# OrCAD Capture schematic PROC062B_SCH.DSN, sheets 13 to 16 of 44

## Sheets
13 12. SoC POWER2: size C; title: SoC POWER2
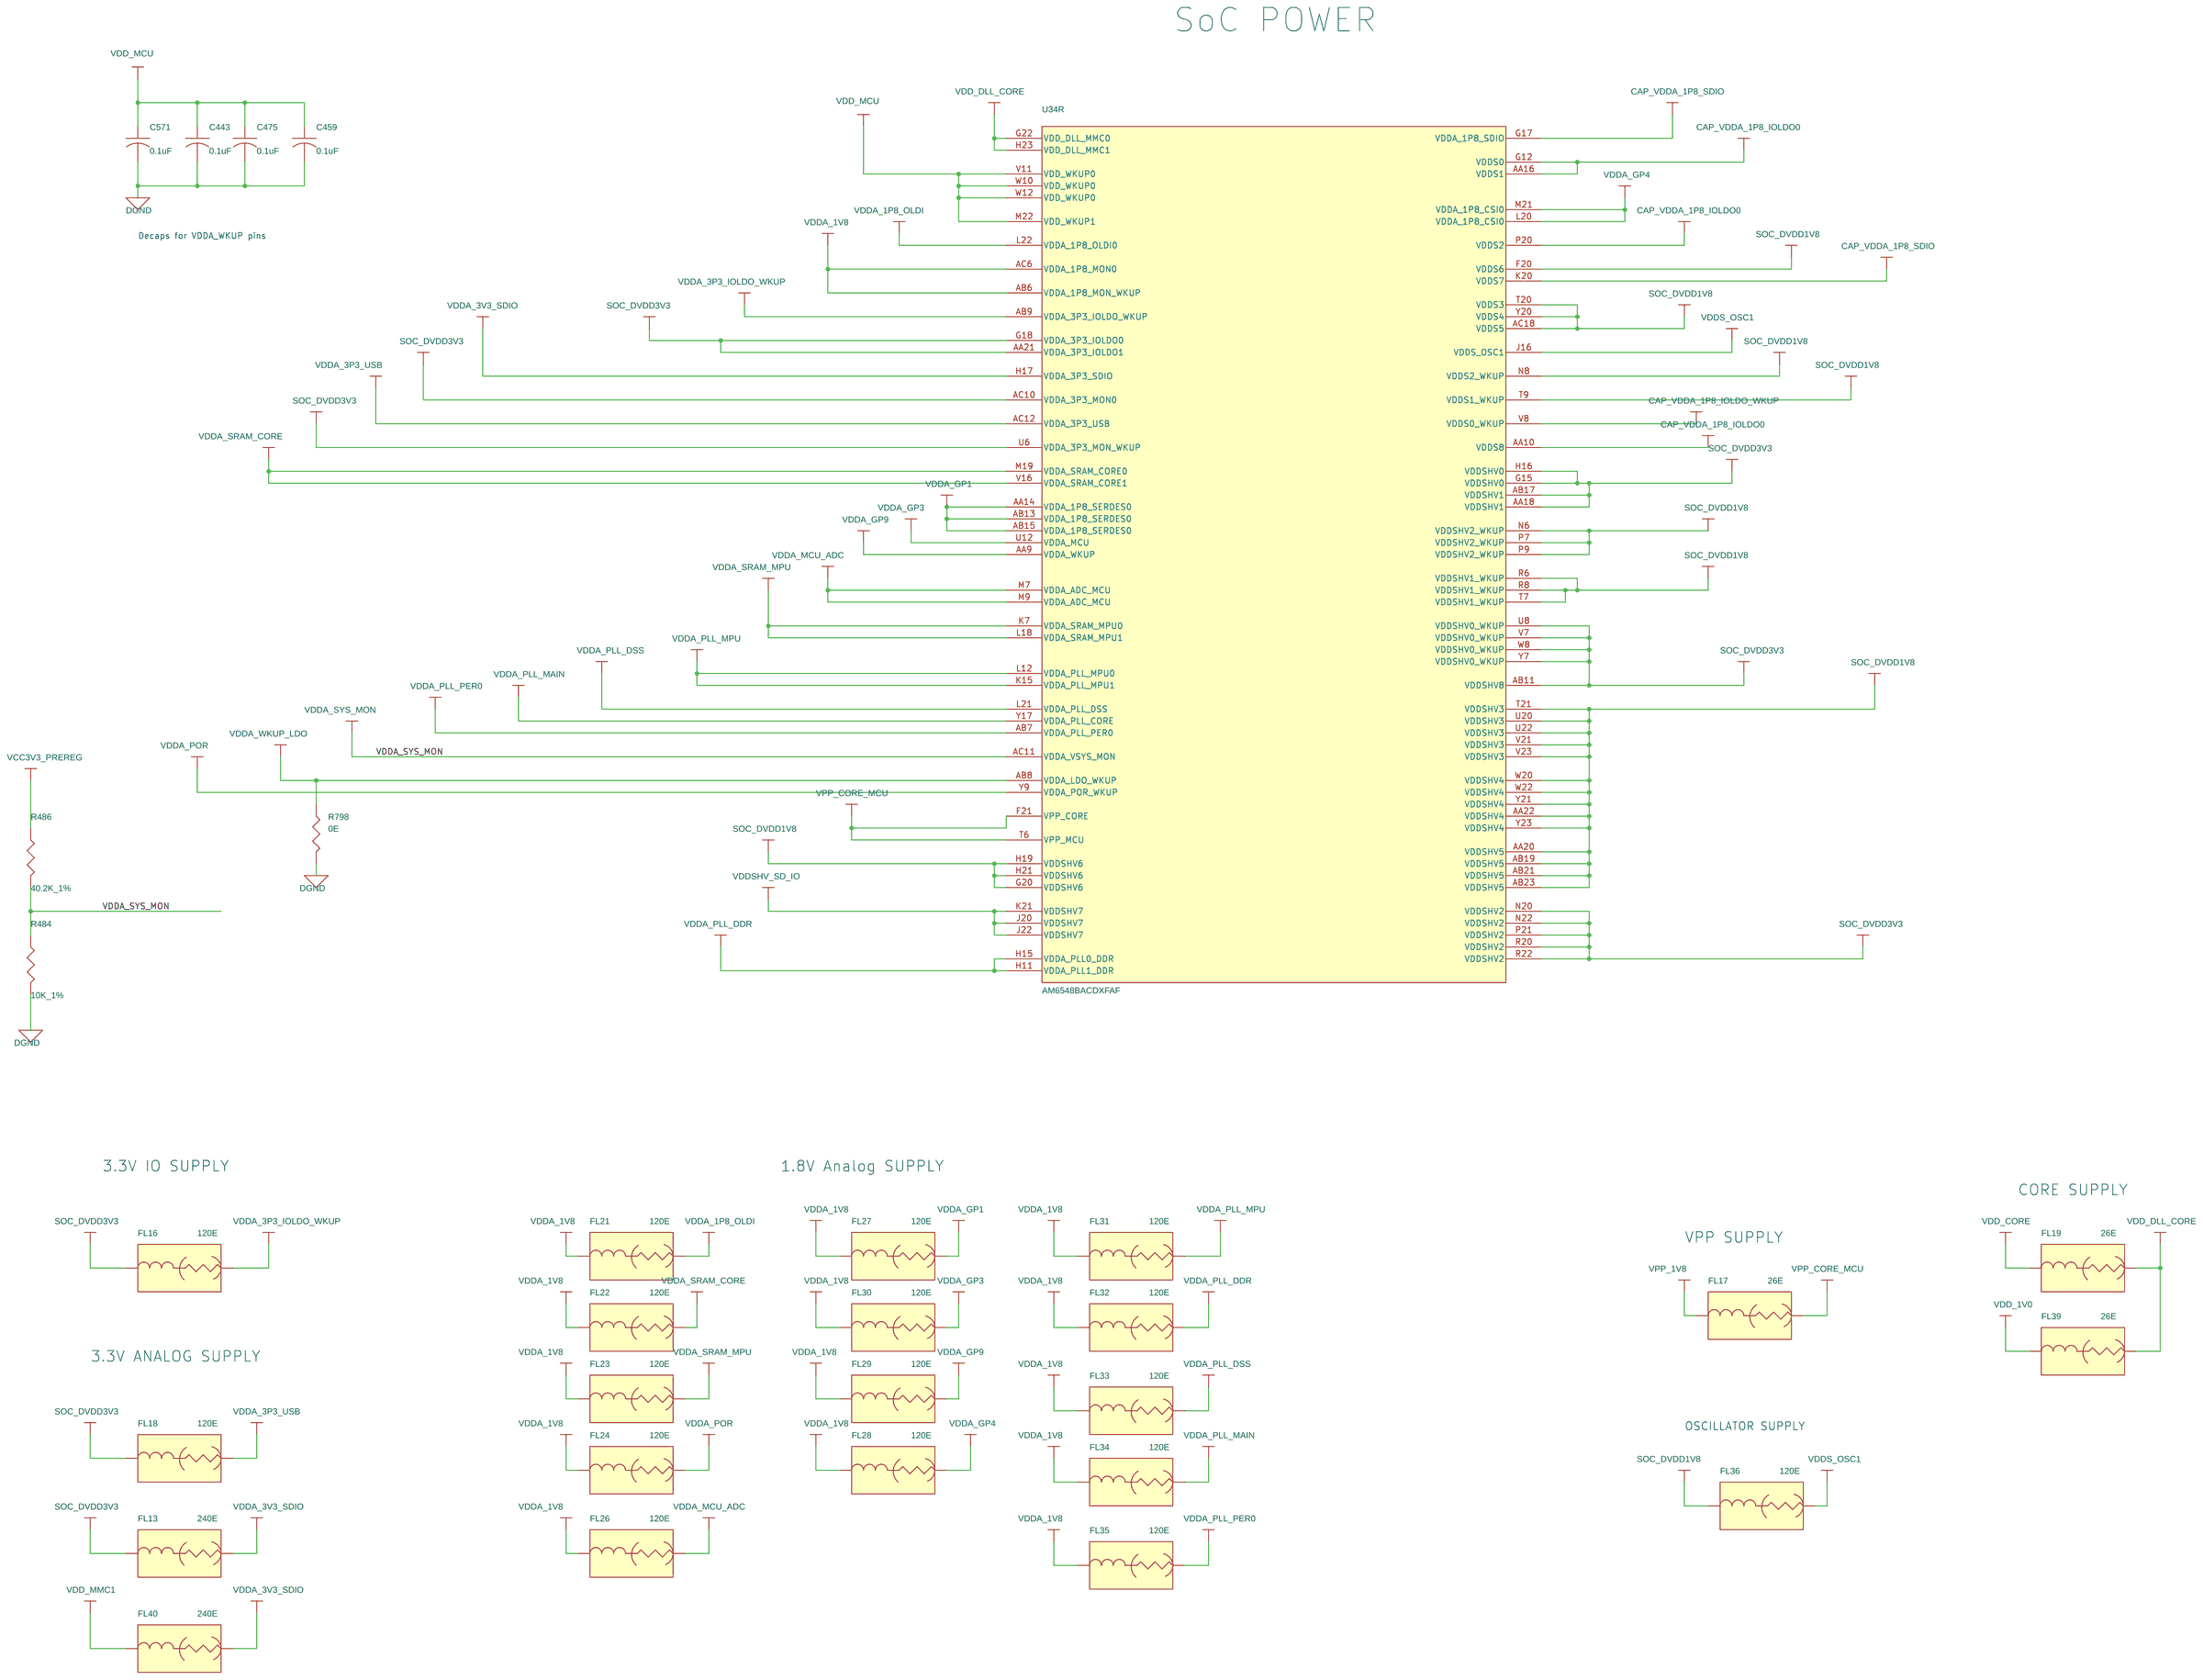
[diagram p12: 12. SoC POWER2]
14 13. SoC POWER3: size C; title: SoC POWER3
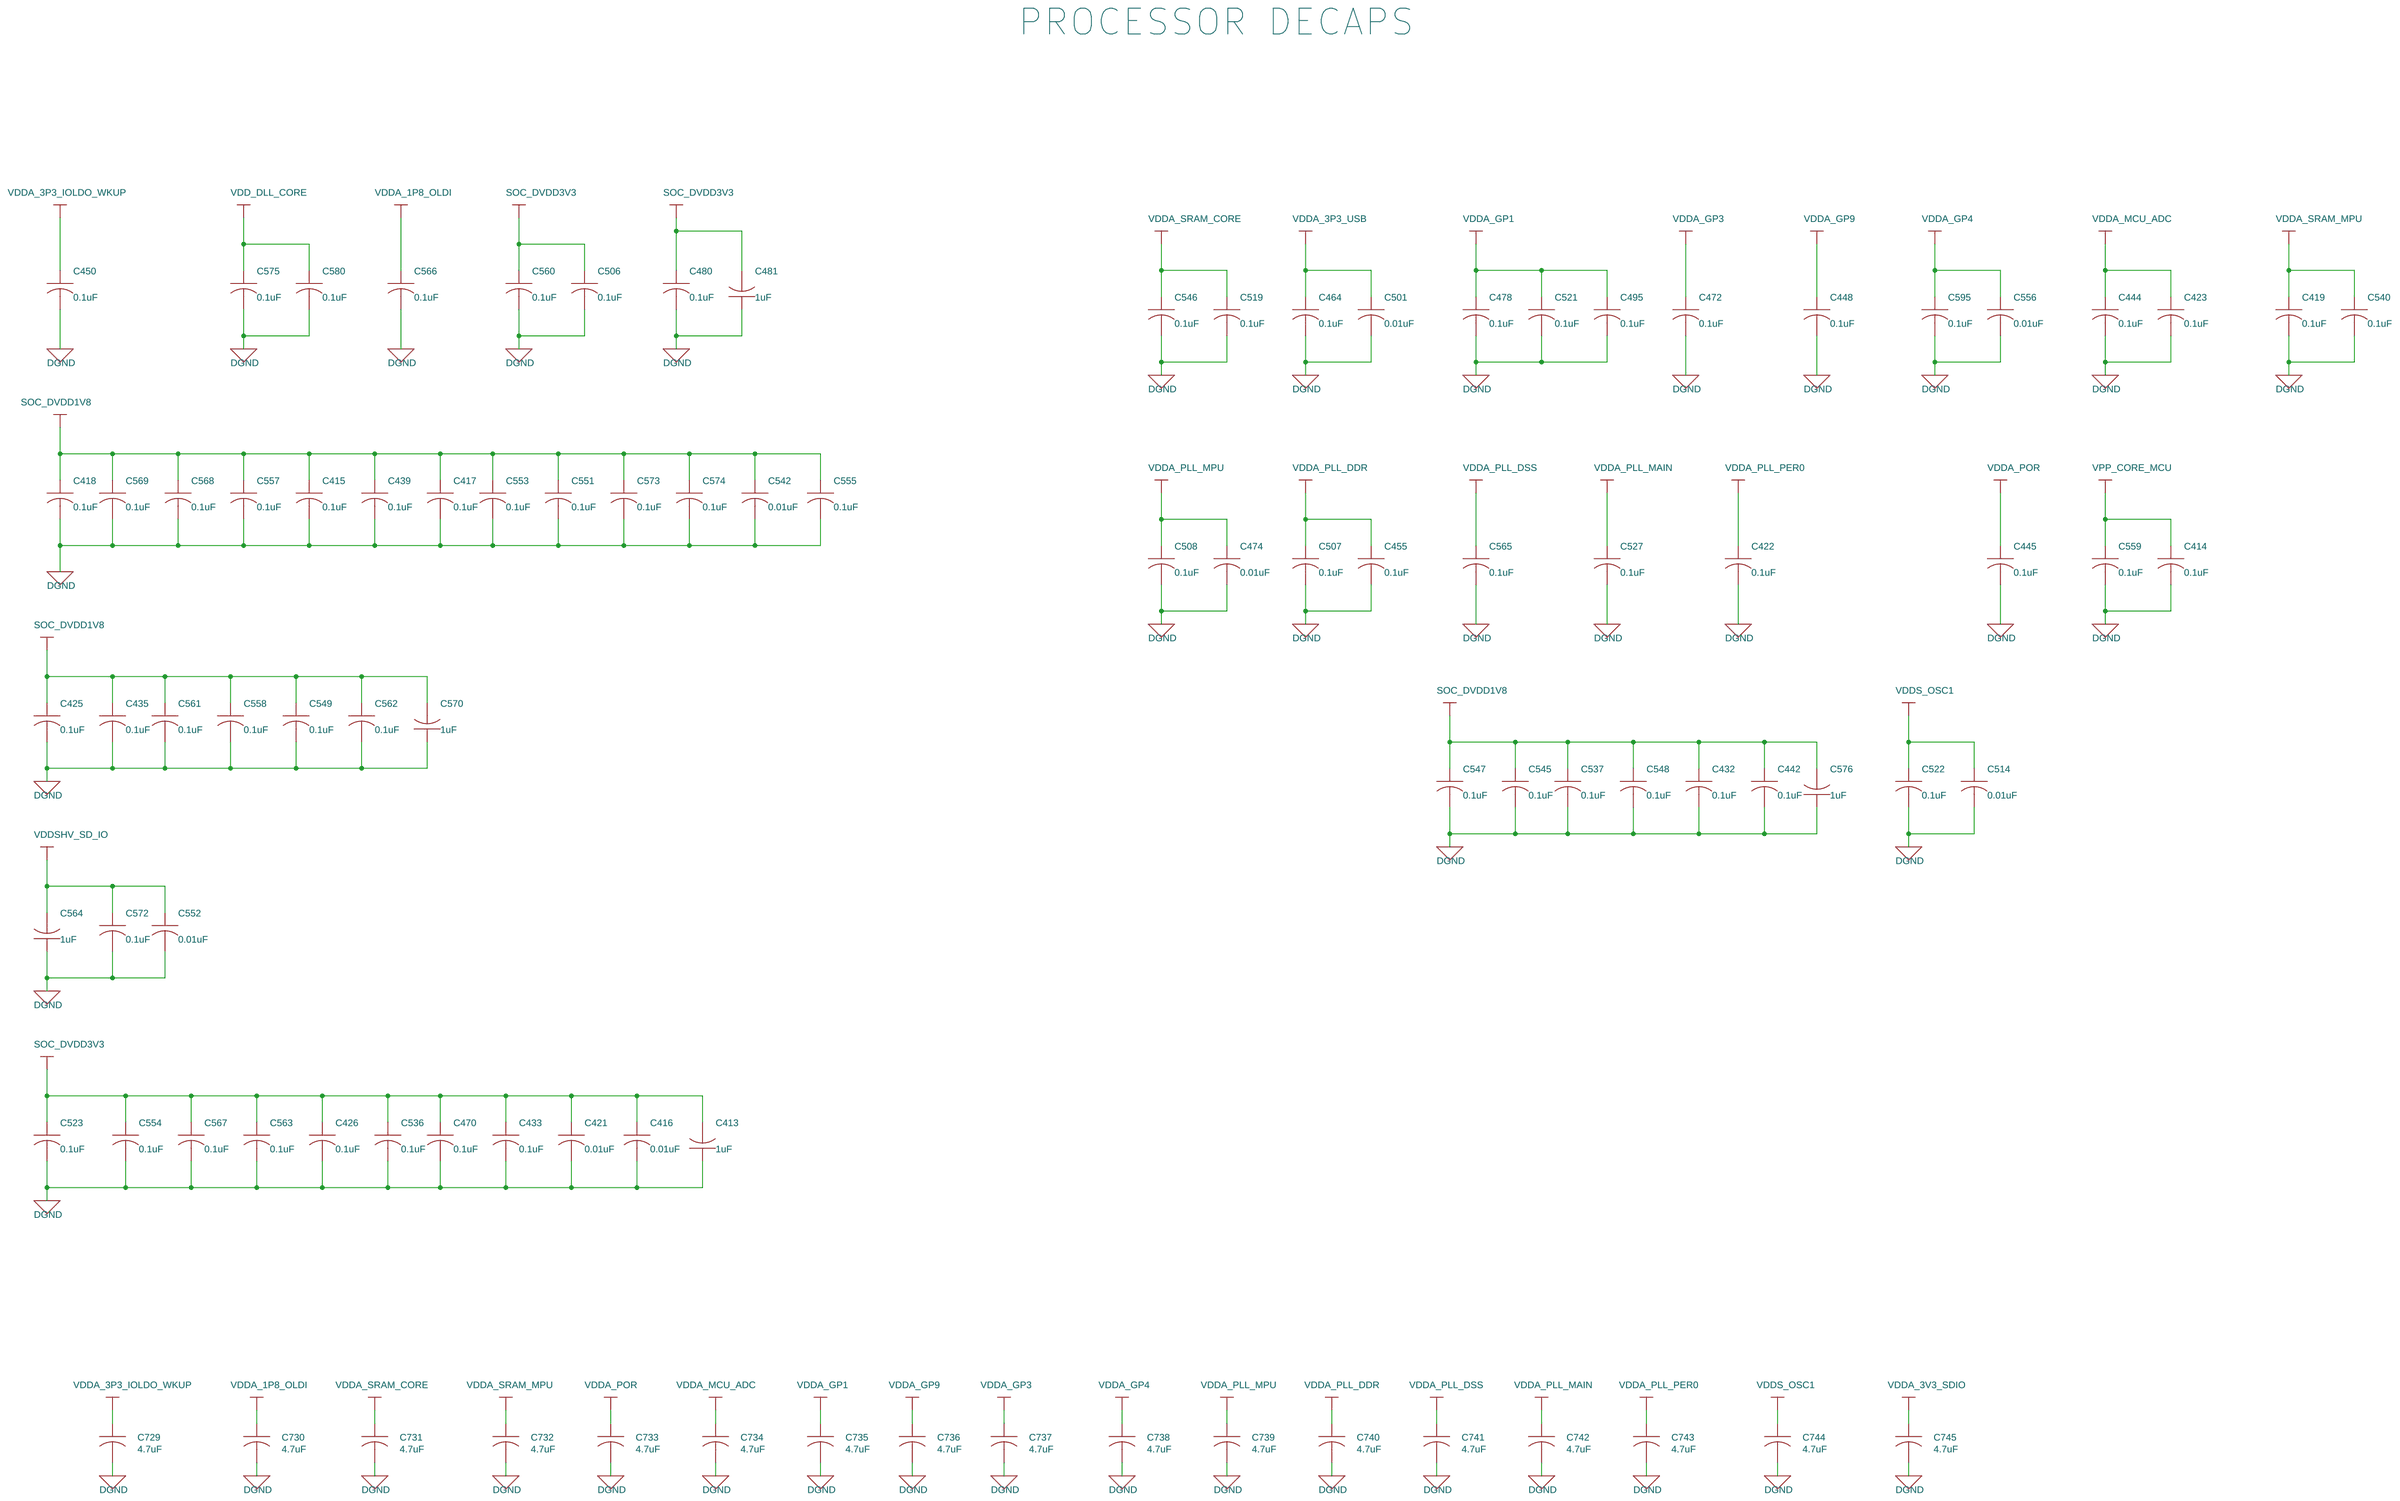
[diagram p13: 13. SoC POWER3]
15 14. SoC POWER4: size C; title: SoC POWER4
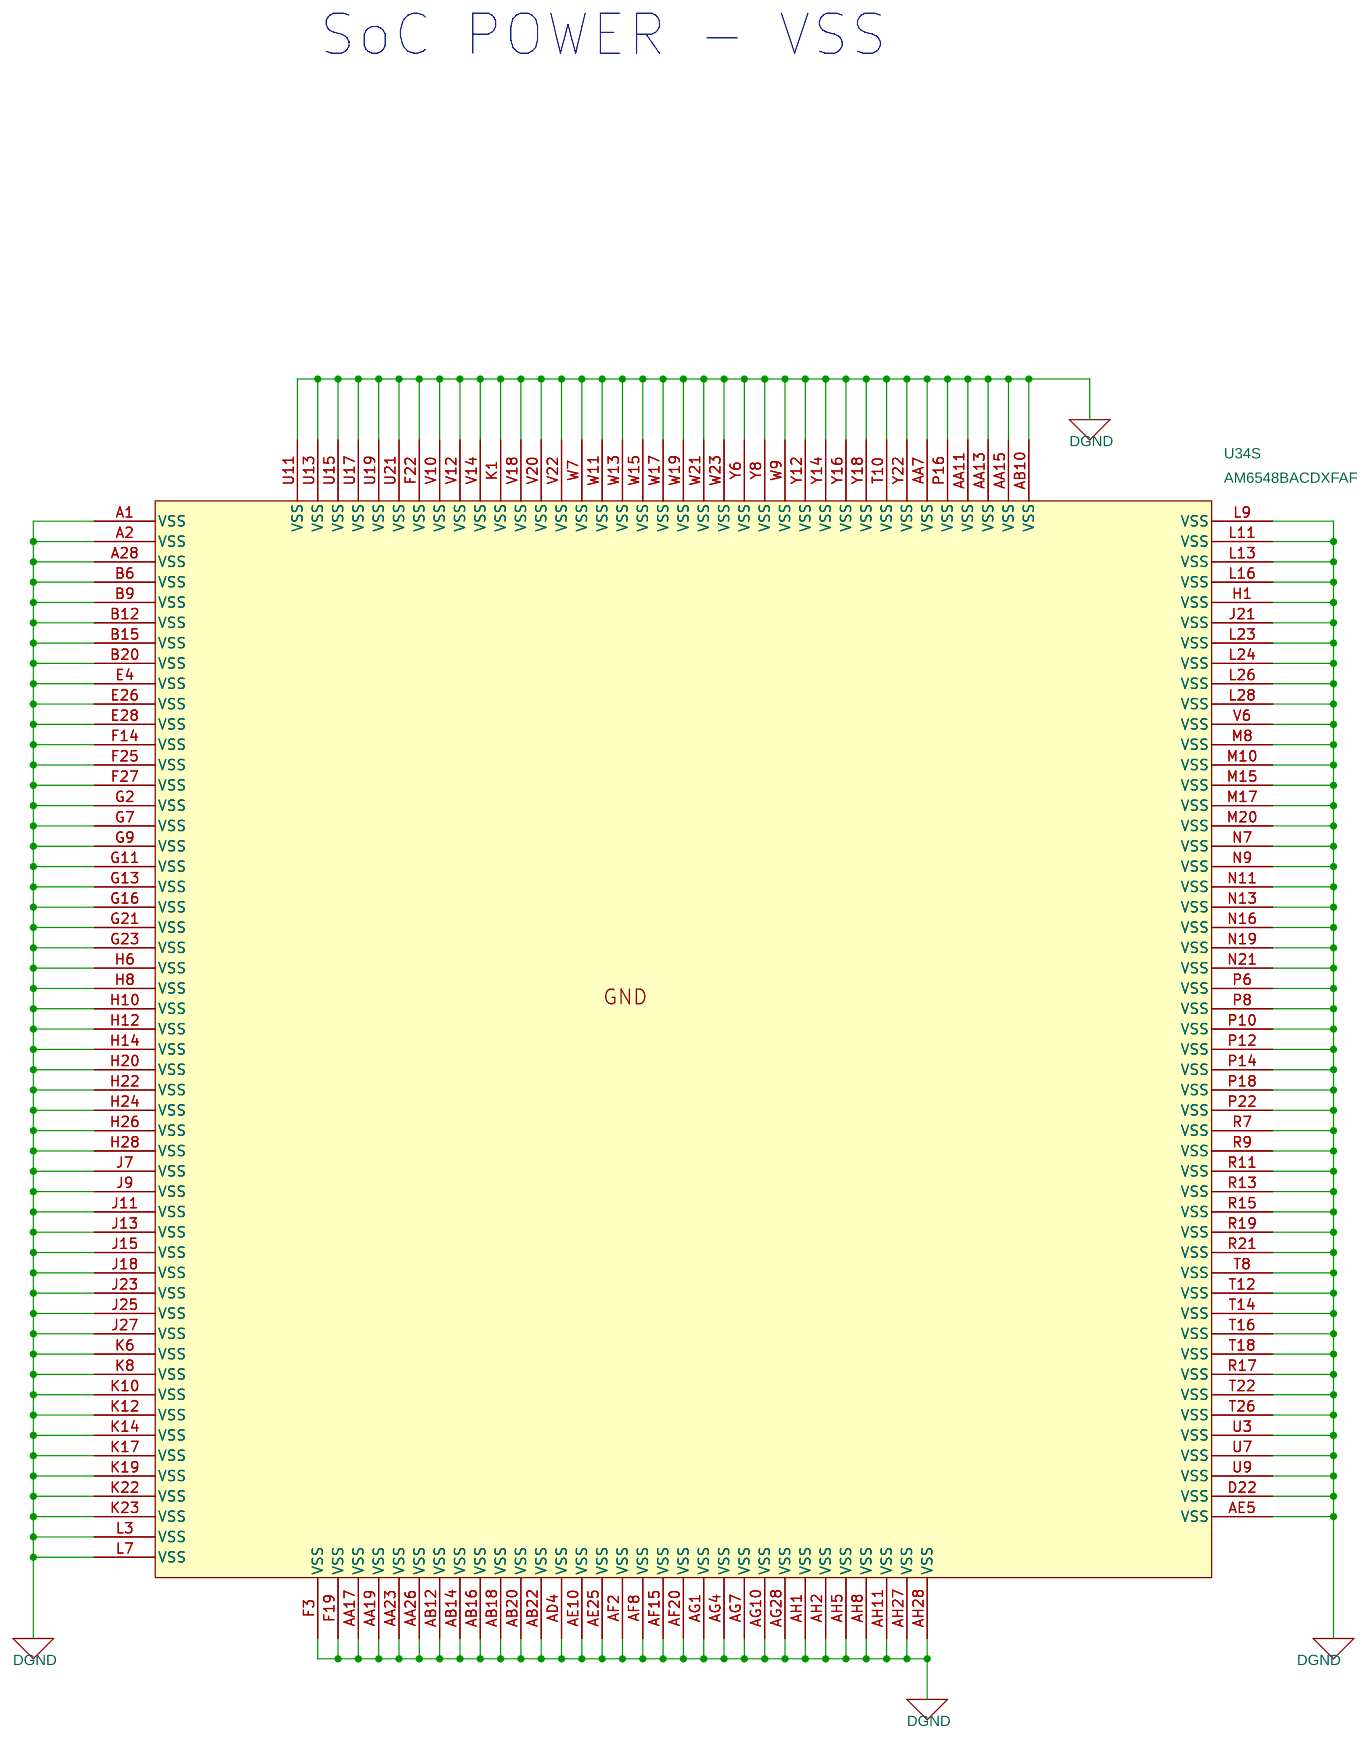
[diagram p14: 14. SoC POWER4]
16 15. DDR4  DEVICES: size C; title: DDR4 DEVICES
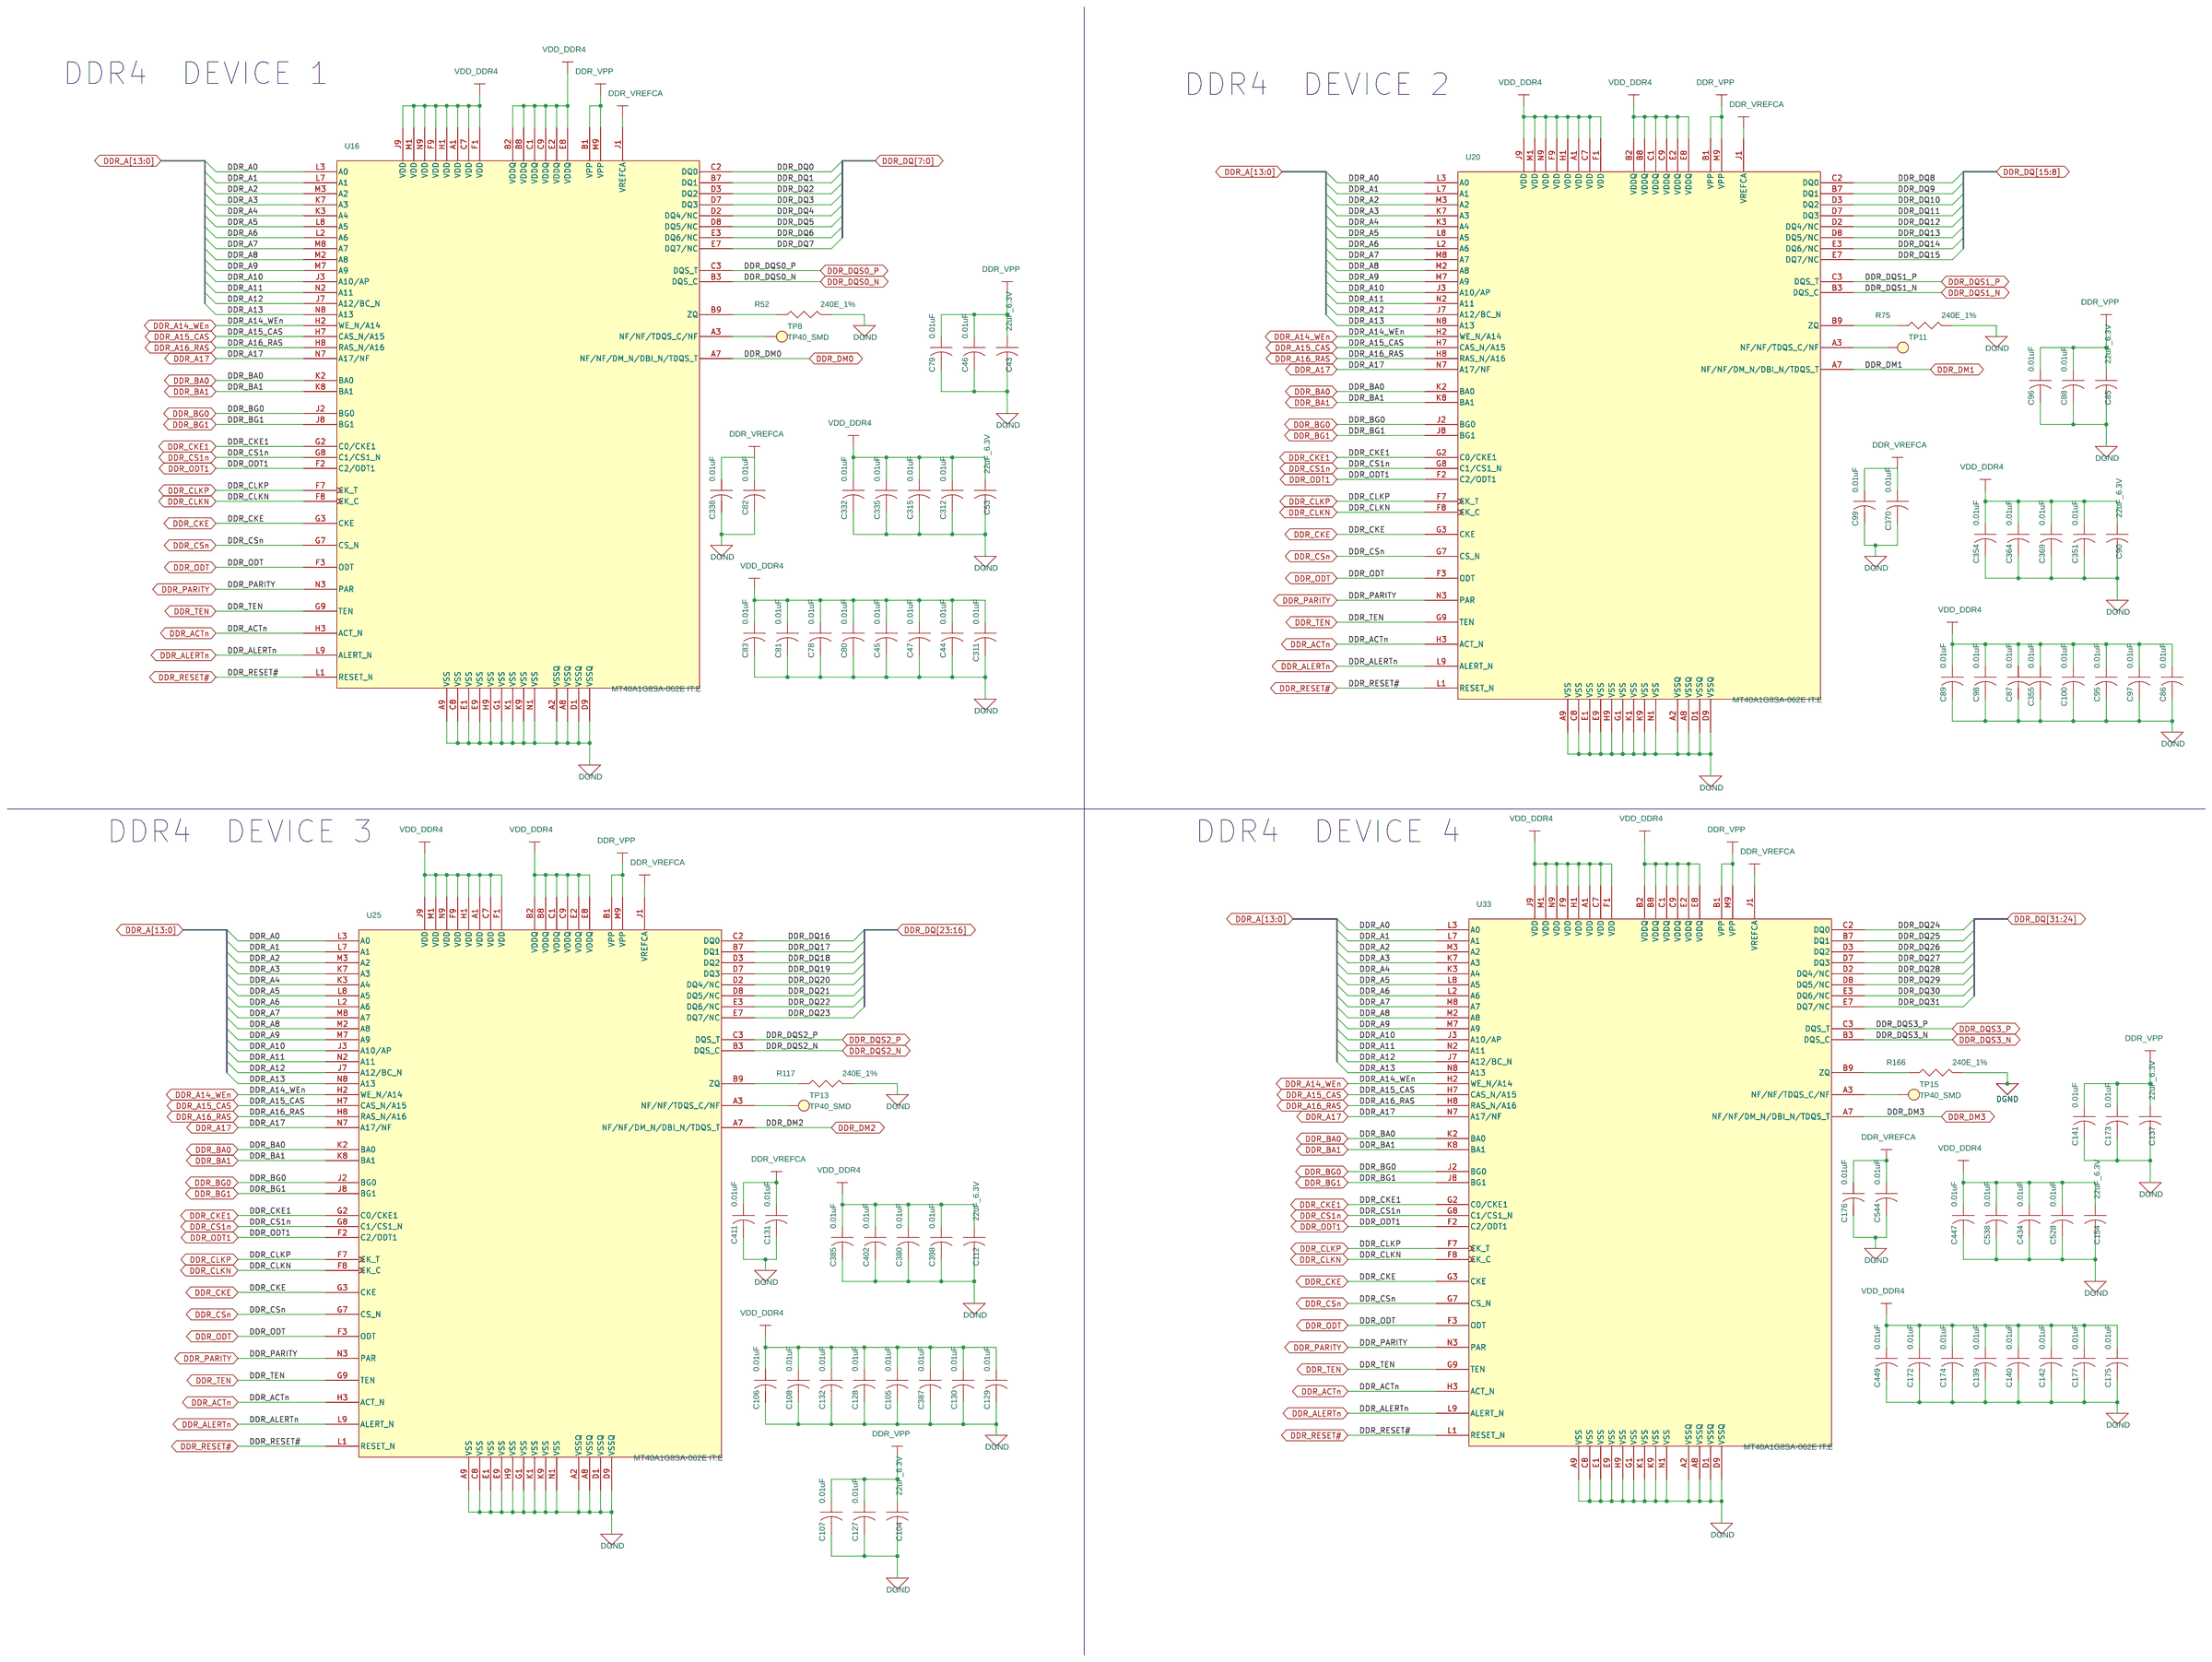
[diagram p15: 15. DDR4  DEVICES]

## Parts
sheet 12. SoC POWER2
C443  0.1uF  [CAP0201_0-5]
C459  0.1uF  [CAP0201_0-5]
C475  0.1uF  [CAP0201_0-5]
C571  0.1uF  [CAP0201_0-5]
FL13  240E  [EMIFIL_BLM03B_0201]
FL16  120E  [EMIFIL_BLM18R_0603_1]
FL17  26E  [EMIFIL_BLM18K_0603]
FL18  120E  [EMIFIL_BLM18R_0603_1]
FL19  26E  [EMIFIL_BLM18K_0603]
FL21  120E  [EMIFIL_BLM18R_0603_1]
FL22  120E  [EMIFIL_BLM18R_0603_1]
FL23  120E  [EMIFIL_BLM18R_0603_1]
FL24  120E  [EMIFIL_BLM18R_0603_1]
FL26  120E  [EMIFIL_BLM18R_0603_1]
FL27  120E  [EMIFIL_BLM18R_0603_1]
FL28  120E  [EMIFIL_BLM18R_0603_1]
FL29  120E  [EMIFIL_BLM18R_0603_1]
FL30  120E  [EMIFIL_BLM18R_0603_1]
FL31  120E  [EMIFIL_BLM18R_0603_1]
FL32  120E  [EMIFIL_BLM18R_0603_1]
FL33  120E  [EMIFIL_BLM18R_0603_1]
FL34  120E  [EMIFIL_BLM18R_0603_1]
FL35  120E  [EMIFIL_BLM18R_0603_1]
FL36  120E  [EMIFIL_BLM18R_0603_1]
FL39  26E  [EMIFIL_BLM18K_0603]
FL40  240E  [EMIFIL_BLM03B_0201]
R484  10K_1%  [RES0402_0-5]
R486  40.2K_1%  [RES0402_0-5]
R798  0E  [RES0201_0-5]
sheet 13. SoC POWER3
C413  1uF  [CAP0402_0-75]
C414  0.1uF  [CAP0201_0-5]
C415  0.1uF  [CAP0201_0-5]
C416  0.01uF  [CAP0201_0-5]
C417  0.1uF  [CAP0201_0-5]
C418  0.1uF  [CAP0201_0-5]
C419  0.1uF  [CAP0201_0-5]
C421  0.01uF  [CAP0201_0-5]
C422  0.1uF  [CAP0201_0-5]
C423  0.1uF  [CAP0201_0-5]
C425  0.1uF  [CAP0201_0-5]
C426  0.1uF  [CAP0201_0-5]
C432  0.1uF  [CAP0201_0-5]
C433  0.1uF  [CAP0201_0-5]
C435  0.1uF  [CAP0201_0-5]
C439  0.1uF  [CAP0201_0-5]
C442  0.1uF  [CAP0201_0-5]
C444  0.1uF  [CAP0201_0-5]
C445  0.1uF  [CAP0201_0-5]
C448  0.1uF  [CAP0201_0-5]
C450  0.1uF  [CAP0201_0-5]
C455  0.1uF  [CAP0201_0-5]
C464  0.1uF  [CAP0201_0-5]
C470  0.1uF  [CAP0201_0-5]
C472  0.1uF  [CAP0201_0-5]
C474  0.01uF  [CAP0201_0-5]
C478  0.1uF  [CAP0201_0-5]
C480  0.1uF  [CAP0201_0-5]
C481  1uF  [CAP0402_0-75]
C495  0.1uF  [CAP0201_0-5]
C501  0.01uF  [CAP0201_0-5]
C506  0.1uF  [CAP0201_0-5]
C507  0.1uF  [CAP0201_0-5]
C508  0.1uF  [CAP0201_0-5]
C514  0.01uF  [CAP0201_0-5]
C519  0.1uF  [CAP0201_0-5]
C521  0.1uF  [CAP0201_0-5]
C522  0.1uF  [CAP0201_0-5]
C523  0.1uF  [CAP0201_0-5]
C527  0.1uF  [CAP0201_0-5]
C536  0.1uF  [CAP0201_0-5]
C537  0.1uF  [CAP0201_0-5]
C540  0.1uF  [CAP0201_0-5]
C542  0.01uF  [CAP0201_0-5]
C545  0.1uF  [CAP0201_0-5]
C546  0.1uF  [CAP0201_0-5]
C547  0.1uF  [CAP0201_0-5]
C548  0.1uF  [CAP0201_0-5]
C549  0.1uF  [CAP0201_0-5]
C551  0.1uF  [CAP0201_0-5]
C552  0.01uF  [CAP0201_0-5]
C553  0.1uF  [CAP0201_0-5]
C554  0.1uF  [CAP0201_0-5]
C555  0.1uF  [CAP0201_0-5]
C556  0.01uF  [CAP0201_0-5]
C557  0.1uF  [CAP0201_0-5]
C558  0.1uF  [CAP0201_0-5]
C559  0.1uF  [CAP0201_0-5]
C560  0.1uF  [CAP0201_0-5]
C561  0.1uF  [CAP0201_0-5]
C562  0.1uF  [CAP0201_0-5]
C563  0.1uF  [CAP0201_0-5]
C564  1uF  [CAP0402_0-75]
C565  0.1uF  [CAP0201_0-5]
C566  0.1uF  [CAP0201_0-5]
C567  0.1uF  [CAP0201_0-5]
C568  0.1uF  [CAP0201_0-5]
C569  0.1uF  [CAP0201_0-5]
C570  1uF  [CAP0402_0-75]
C572  0.1uF  [CAP0201_0-5]
C573  0.1uF  [CAP0201_0-5]
C574  0.1uF  [CAP0201_0-5]
C575  0.1uF  [CAP0201_0-5]
C576  1uF  [CAP0402_0-75]
C580  0.1uF  [CAP0201_0-5]
C595  0.1uF  [CAP0201_0-5]
C729  4.7uF  [CAP0603_1]
C730  4.7uF  [CAP0603_1]
C731  4.7uF  [CAP0603_1]
C732  4.7uF  [CAP0603_1]
C733  4.7uF  [CAP0603_1]
C734  4.7uF  [CAP0603_1]
C735  4.7uF  [CAP0603_1]
C736  4.7uF  [CAP0603_1]
C737  4.7uF  [CAP0603_1]
C738  4.7uF  [CAP0603_1]
C739  4.7uF  [CAP0603_1]
C740  4.7uF  [CAP0603_1]
C741  4.7uF  [CAP0603_1]
C742  4.7uF  [CAP0603_1]
C743  4.7uF  [CAP0603_1]
C744  4.7uF  [CAP0603_1]
C745  4.7uF  [CAP0603_1]
sheet 15. DDR4  DEVICES
C43  22uF_6.3V  [CAP0603]
C44  0.01uF  [CAP0201_0-5]
C45  0.01uF  [CAP0201_0-5]
C46  0.01uF  [CAP0201_0-5]
C47  0.01uF  [CAP0201_0-5]
C53  22uF_6.3V  [CAP0603]
C78  0.01uF  [CAP0201_0-5]
C79  0.01uF  [CAP0201_0-5]
C80  0.01uF  [CAP0201_0-5]
C81  0.01uF  [CAP0201_0-5]
C82  0.01uF  [CAP0201_0-5]
C83  0.01uF  [CAP0201_0-5]
C85  22uF_6.3V  [CAP0603]
C86  0.01uF  [CAP0201_0-5]
C87  0.01uF  [CAP0201_0-5]
C88  0.01uF  [CAP0201_0-5]
C89  0.01uF  [CAP0201_0-5]
C90  22uF_6.3V  [CAP0603]
C95  0.01uF  [CAP0201_0-5]
C96  0.01uF  [CAP0201_0-5]
C97  0.01uF  [CAP0201_0-5]
C98  0.01uF  [CAP0201_0-5]
C99  0.01uF  [CAP0201_0-5]
C100  0.01uF  [CAP0201_0-5]
C104  22uF_6.3V  [CAP0603]
C105  0.01uF  [CAP0201_0-5]
C106  0.01uF  [CAP0201_0-5]
C107  0.01uF  [CAP0201_0-5]
C108  0.01uF  [CAP0201_0-5]
C112  22uF_6.3V  [CAP0603]
C127  0.01uF  [CAP0201_0-5]
C128  0.01uF  [CAP0201_0-5]
C129  0.01uF  [CAP0201_0-5]
C130  0.01uF  [CAP0201_0-5]
C131  0.01uF  [CAP0201_0-5]
C132  0.01uF  [CAP0201_0-5]
C137  22uF_6.3V  [CAP0603]
C139  0.01uF  [CAP0201_0-5]
C140  0.01uF  [CAP0201_0-5]
C141  0.01uF  [CAP0201_0-5]
C142  0.01uF  [CAP0201_0-5]
C154  22uF_6.3V  [CAP0603]
C172  0.01uF  [CAP0201_0-5]
C173  0.01uF  [CAP0201_0-5]
C174  0.01uF  [CAP0201_0-5]
C175  0.01uF  [CAP0201_0-5]
C176  0.01uF  [CAP0201_0-5]
C177  0.01uF  [CAP0201_0-5]
C311  0.01uF  [CAP0201_0-5]
C312  0.01uF  [CAP0201_0-5]
C315  0.01uF  [CAP0201_0-5]
C332  0.01uF  [CAP0201_0-5]
C335  0.01uF  [CAP0201_0-5]
C338  0.01uF  [CAP0201_0-5]
C351  0.01uF  [CAP0201_0-5]
C354  0.01uF  [CAP0201_0-5]
C355  0.01uF  [CAP0201_0-5]
C364  0.01uF  [CAP0201_0-5]
C369  0.01uF  [CAP0201_0-5]
C370  0.01uF  [CAP0201_0-5]
C380  0.01uF  [CAP0201_0-5]
C385  0.01uF  [CAP0201_0-5]
C387  0.01uF  [CAP0201_0-5]
C398  0.01uF  [CAP0201_0-5]
C402  0.01uF  [CAP0201_0-5]
C411  0.01uF  [CAP0201_0-5]
C434  0.01uF  [CAP0201_0-5]
C447  0.01uF  [CAP0201_0-5]
C449  0.01uF  [CAP0201_0-5]
C528  0.01uF  [CAP0201_0-5]
C538  0.01uF  [CAP0201_0-5]
C544  0.01uF  [CAP0201_0-5]
R52  240E_1%  [RES0402]
R75  240E_1%  [RES0402]
R117  240E_1%  [RES0402]
R166  240E_1%  [RES0402]
TP8  TP40_SMD  [TP40_SMD]
TP11  TP40_SMD  [TP40_SMD]
TP13  TP40_SMD  [TP40_SMD]
TP15  TP40_SMD  [TP40_SMD]
U16  MT40A1G8SA-062E IT:E  [FBGA78_31-49_300X440_1-2]
U20  MT40A1G8SA-062E IT:E  [FBGA78_31-49_300X440_1-2]
U25  MT40A1G8SA-062E IT:E  [FBGA78_31-49_300X440_1-2]
U33  MT40A1G8SA-062E IT:E  [FBGA78_31-49_300X440_1-2]
sheet 16. DDR4 ECC & TERMINATIONS
U34  AM6548BACDXFAF  [BGA784_31-49_910X910_1-7]  (sections A,B,C,D,E,F,G,H,I,J,K,L,M,N,O,P,Q,R,S)

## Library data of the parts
C414 C415 C417-C419 C422 C423 C425 C426 C432 C433 C435 C439 C442-C445 C448 C450 C455 C459 C464 C470 C472 C475 C478 C480 C495 C506-C508 C519 C521-C523 C527 C536 C537 C540 C545-C549 C551 C553-C555 C557-C563 C565-C569 C571-C575 C580 C595 = CAP: CAP CERAMIC 0.1uF 16V 10% X5R 0201; Chkd/date: MANIRAJA/120218; Crtd /date: MANIRAJA/120218; Custom_Duty: 15%; Customs_HS_Code: 85322990; Distributor_name: DIGIKEY; Distributor_part_number: 490-16742-1-ND; Height: 0.33MM; Mfr_name: MURATA; Mfr_part_number: GRM033R61C104KE84J; Mistral Part No: 120009030072-R; Package: 0201; Part_type: CAPACITORS\CERAMIC; Project: TI_MAXIE_CPB; RoHS: RoHS; Temperature: -55°C+85°C; Tolerance: 10%; Voltage: 16V; Wattage: NA; Weight: 0.33mg; Datasheet: Y:\MIS_DATABASE\DATASHEETS\CAPACITORS\GRM033R61C104KE84.PDF
FL13 FL40 = EMIFILTER_IND: FERRITE CHIP 240E 350mA 0201; Chkd/date: VASANTHA/070814; Crtd /date: NAVEED/140714; Custom_Duty: 24%; Customs_HS_Code: 85437099; Distributor_name: DIGIKEY; Distributor_part_number: 490-5623-1-ND; Height: 0.33MM; Mfr_name: MURATA; Mfr_part_number: BLM03AX241SN1D; Mistral Part No: 130014070021-R; Package: 0201; Part_type: MISC\FILTER; Project: HUMANWARE_PHOENIX; RoHS: RoHS; Temperature: -55°C+125°C; Tolerance: NA; Voltage: NA; Wattage: NA; Weight: NA; Datasheet: Y:\MIS_DATABASE\DATASHEETS\DISCRETES\INDUCTORS\BLM03AX.PDF
FL16 FL18 FL21-FL24 FL26-FL36 = EMIFILTER_IND: FERRITE BEAD 120E 2A 0603; Chkd/date: VASANTHA/061216; Crtd /date: MUDDU/190610; Custom_Duty: 24%; Customs_HS_Code: 85437099; Distributor_name: DIGIKEY; Distributor_part_number: 490-3991-1-ND; Footprint Path: Y:\MIS_DATABASE\Library\ALTIUM_TOOL\PCB_FOOTPRINTS\Altium_Footprint_Lib.PcbLib; Height: 0.95MM; Library Path: Y:\MIS_DATABASE\Library\ALTIUM_TOOL\SCHEMATICS_PARTS\MS_FILTER_Library.schlib; Mfr_name: MURATA; Mfr_part_number: BLM18EG121SN1D; Mistral Part No: 130010060030-R; Package: 0603; Part_type: MISC\FILTER; Project: CENTAURUS; RoHS: RoHS; Temperature: -55°C+125°C; Tolerance: NA; Voltage: NA; Wattage: NA; Weight: NA; Datasheet: Y:\MIS_DATABASE\DATASHEETS\DISCRETES\INDUCTORS\BLM18E.PDF
FL17 FL19 FL39 = EMIFILTER_IND: FERRITE CHIP 26E 6A 0603; Chkd/date: USMAN/020112; Crtd /date: CHAITHANYA/020112; Custom_Duty: 24%; Customs_HS_Code: 85437099; Distributor_name: DIGIKEY; Distributor_part_number: 490-5252-1-ND; Height: 0.75MM; Mfr_name: MURATA; Mfr_part_number: BLM18KG260TN1D; Mistral Part No: 130012010003-R; Package: 0603; Part_type: MISC\FILTER; Project: NA10NG; RoHS: RoHS; Temperature: -55°C+125°C; Tolerance: NA; Voltage: NA; Wattage: NA; Weight: NA; Datasheet: Y:\MIS_DATABASE\DATASHEETS\DISCRETES\INDUCTORS\BLM18K-SERIES.PDF
R484 = RESISTOR: RES 10K 1/16W 1% 0402; Chkd/date: VASANTHA/201216; Crtd /date: GEETHA/290506; Custom_Duty: 15%; Customs_HS_Code: 85332119; Distributor_name: DIGIKEY; Distributor_part_number: 311-10.0KLRTR-ND; Footprint Path: Y:\MIS_DATABASE\Library\ALTIUM_TOOL\PCB_FOOTPRINTS\Altium_Footprint_Lib.PcbLib; Height: 0.40MM; Library Path: Y:\MIS_DATABASE\Library\ALTIUM_TOOL\SCHEMATICS_PARTS\MS_DISCRETE_Library.schlib; Mfr_name: YAGEO AMERICA; Mfr_part_number: RC0402FR-0710KL; Mistral Part No: 110009030220-P; Package: 0402; Part_type: RESISTORS\FIXED; Project: VOCERA; RoHS: Pb-Free; Temperature: -55°C+155°C; Tolerance: 1%; Voltage: NA; Wattage: 1/16W; Weight: 0.65mg; Datasheet: Y:\MIS_DATABASE\DATASHEETS\RESISTORS\YAGEO-RC0402.PDF
R486 = RESISTOR: RES 40.2K 1/16W 1% 0402; Chkd/date: VASANTHA/291216; Crtd /date: MAZHAR/170505; Custom_Duty: 15%; Customs_HS_Code: 85332119; Distributor_name: DIGIKEY; Distributor_part_number: 311-40.2KLRDKR-ND; Footprint Path: Y:\MIS_DATABASE\Library\ALTIUM_TOOL\PCB_FOOTPRINTS\Altium_Footprint_Lib.PcbLib; Height: 0.40MM; Library Path: Y:\MIS_DATABASE\Library\ALTIUM_TOOL\SCHEMATICS_PARTS\MS_DISCRETE_Library.schlib; Mfr_name: YAGEO AMERICA; Mfr_part_number: RC0402FR-0740K2L; Mistral Part No: 110009030811; Package: 0402; Part_type: RESISTORS\FIXED; Project: G4SLIM; RoHS: RoHS; Temperature: -55°C+155°C; Tolerance: 1%; Voltage: NA; Wattage: 1/16W; Weight: 0.65mg; Datasheet: Y:\MIS_DATABASE\DATASHEETS\RESISTORS\YAGEO_RES.PDF
R798 = RESISTOR: RES 0E 1/20W 5% 0201; Chkd/date: NAVEED/301214; Crtd /date: MUDDU/120710; Custom_Duty: 15%; Customs_HS_Code: 85332119; Distributor_name: DIGIKEY; Distributor_part_number: 311-0.0NCT-ND; Footprint Path: Y:\MIS_DATABASE\Library\ALTIUM_TOOL\PCB_FOOTPRINTS\Altium_Footprint_Lib.PcbLib; Height: 0.26MM; Library Path: Y:\MIS_DATABASE\Library\ALTIUM_TOOL\SCHEMATICS_PARTS\MS_DISCRETE_Library.schlib; Mfr_name: YAGEO AMERICA; Mfr_part_number: RC0201JR-070RL; Mistral Part No: 110010070067-R; Package: 0201; Part_type: RESISTORS\FIXED; Project: PB_BUGBASE; RoHS: RoHS; Temperature: -55°C+125°C; Tolerance: 5%; Voltage: NA; Wattage: 1/20W; Weight: 0.17mg; Datasheet: Y:\MIS_DATABASE\DATASHEETS\RESISTORS\RCXXXXL-SER_MAR18.PDF
C413 C481 C564 C570 C576 = CAP: CAP CERAMIC 1uF 16V 20% X5R 0402; Chkd/date: MANIRAJA/150218; Crtd /date: ALVY/150218; Custom_Duty: 15%; Customs_HS_Code: 85322990; Distributor_name: DIGIKEY; Distributor_part_number: 587-5514-1-ND; Footprint Path: Y:\MIS_DATABASE\Library\ALTIUM_TOOL\PCB_FOOTPRINTS\Altium_Footprint_Lib.PcbLib; Height: 0.55MM; Library Path: Y:\MIS_DATABASE\Library\ALTIUM_TOOL\SCHEMATICS_PARTS\MS_DISCRETE_Library.schlib; Mfr_name: TAIYO YUDEN; Mfr_part_number: EMK105BJ105MV-F; Mistral Part No: 120018020006-R; Package: 0402; Part_type: CAPACITORS\CERAMIC; Project: TI_MAXIE_CPB; RoHS: RoHS; Temperature: -55°C+85°C; Tolerance: 20%; Voltage: 16V; Wattage: NA; Weight: 0.65mg; Datasheet: Y:\MIS_DATABASE\DATASHEETS\CAPACITORS\EMK105BJ105MV-F.PDF
C44-C47 C78-C83 C86-C89 C95-C100 C105-C108 C127-C132 C139-C142 C172-C177 C311 C312 C315 C332 C335 C338 C351 C354 C355 C364 C369 C370 C380 C385 C387 C398 C402 C411 C416 C421 C434 C447 C449 C474 C501 C514 C528 C538 C542 C544 C552 C556 = CAP: CAP CERAMIC 0.01uF 25V 10% X5R 0201; Chkd/date: MANIRAJA/230118; Crtd /date: MANIRAJA/230118; Custom_Duty: 15%; Customs_HS_Code: 85322990; Distributor_name: DIGIKEY; Distributor_part_number: GRM033R61E103KA12J-ND; Height: 0.33MM; Mfr_name: MURATA; Mfr_part_number: GRM033R61E103KA12J; Mistral Part No: 120018010007-R; Package: 0201; Part_type: CAPACITORS\CERAMIC; Project: TI_MAXIE_CPB; RoHS: RoHS; Temperature: -55°C+85°C; Tolerance: 10%; Voltage: 25V; Wattage: NA; Weight: 0.33mg; Datasheet: Y:\MIS_DATABASE\DATASHEETS\CAPACITORS\GRM033R61E103KA12.PDF
C729-C745 = CAP: CAP CERAMIC 4.7uF 16V 10% X5R 0603; Chkd/date: MANIRAJA/131217; Crtd /date: ALVY/131217; Custom_Duty: 15%; Customs_HS_Code: 85322990; Distributor_name: DIGIKEY; Distributor_part_number: 311-1785-1-ND; Footprint Path: Y:\MIS_DATABASE\Library\ALTIUM_TOOL\PCB_FOOTPRINTS\Altium_Footprint_Lib.PcbLib; Height: 0.95MM; Library Path: Y:\MIS_DATABASE\Library\ALTIUM_TOOL\SCHEMATICS_PARTS\MS_DISCRETE_Library.schlib; Mfr_name: YAGEO AMERICA; Mfr_part_number: CC0603KRX5R7BB475; Mistral Part No: 120011050004-R; Package: 0603; Part_type: CAPACITORS\CERAMIC; Project: ASL_LIU_TYPE-II; RoHS: RoHS; Temperature: -55°C+85°C; Tolerance: 10%; Voltage: 16V; Wattage: NA; Weight: 2mg; Datasheet: Y:\MIS_DATABASE\DATASHEETS\CAPACITORS\YACC-X5R.PDF
C43 C53 C85 C90 C104 C112 C137 C154 = CAP: CAP CERAMIC 22uF 6.3V 20% X5R 0603; Alternate_mfr_name_A: YAGEO AMERICA; Alternate_mfr_part_number_A: CC0603MRX5R5BB226; Chkd/date: JEBRAN/090915; Crtd /date: JEBRAN/090915; Custom_Duty: 15%; Customs_HS_Code: 85322990; Distributor_name: DIGIKEY; Distributor_name_A: DIGIKEY; Distributor_part_number: 490-7611-2-ND; Distributor_part_number_A: 311-1815-1-ND; Height: 1.00MM; Mfr_name: MURATA; Mfr_part_number: GRM188R60J226MEA0; Mistral Part No: 120015090007-R; Package: 0603; Part_type: CAPACITORS\CERAMIC; Project: OCTBTS_3000; RoHS: RoHS; Temperature: -55°C+85°C; Tolerance: 20%; Voltage: 6.3V; Wattage: NA; Weight: NA; Datasheet: Y:\MIS_DATABASE\DATASHEETS\CAPACITORS\GRM188SERIES.PDF
R52 R75 R117 R166 = RESISTOR: RES 240E 1/10W 1% 0402; Chkd/date: MAZHAR/150611; Crtd /date: BAVISH/020611; Custom_Duty: 15%; Customs_HS_Code: 85332119; Distributor_name: DIGIKEY; Distributor_part_number: P240LCT-ND; Height: 0.40MM; Mfr_name: PANASONIC-ECG; Mfr_part_number: ERJ-2RKF2400X; Mistral Part No: 110011060017-R; Package: 0402; Part_type: RESISTORS\FIXED; Project: AM4515_EVM_LCD; RoHS: RoHS; Temperature: -55°C+125°C; Tolerance: 1%; Voltage: NA; Wattage: 1/10W; Weight: 0.8/1000g; Datasheet: Y:\MIS_DATABASE\DATASHEETS\RESISTORS\ERJ-2R.PDF
TP8 TP11 TP13 TP15 = TESTPOINT: TESTPOINT CIR 40 SMD; Chkd/date: MAZHAR/190505; Crtd /date: MAZHAR/190505; Distributor_name: NA; Distributor_part_number: NA; Footprint Path: Y:\MIS_DATABASE\Library\ALTIUM_TOOL\PCB_FOOTPRINTS\Altium_Footprint_Lib.PcbLib; Height: NA; Library Path: Y:\MIS_DATABASE\Library\ALTIUM_TOOL\SCHEMATICS_PARTS\MS_DISCRETE_Library.schlib; MECHANICAL 3D STEP FILE: NA; Mfr_name: LOCAL; Mistral Part No: 130009030933; Package: SMD; Project: RAINIER-3; RoHS: NA; Temperature: NA; Tolerance: NA; Voltage: NA; Wattage: NA; Weight: NA; Datasheet: NA
U16 U20 U25 U33 = MT40A1G8WE-083_FBGA78: IC 1G8 DDR4 SDRAM MEMORY FBGA78; Chkd/date: MANIRAJA/010819; Crtd /date: ALVY/010819; Custom_Duty: 15%; Customs_HS_Code: 85423100; Distributor_name: DIGIKEY; Distributor_part_number: MT40A1G8SA-062EIT:E-ND; Footprint Path: Y:\MIS_DATABASE\Library\ALTIUM_TOOL\PCB_FOOTPRINTS\Altium_Footprint_Lib.PcbLib; Height: 1.20MM; Library Path: Y:\MIS_DATABASE\Library\ALTIUM_TOOL\SCHEMATICS_PARTS\MS_MISCMEMORY_Library.schlib; Mfr_name: MICRON; Mistral Part No: 141119080001-R; Package: FBGA78; Part_type: ICS\DIGITAL\MEMORY; Project: TI_MAXIE_CPB; RoHS: RoHS; Temperature: -40°C+95°C; Tolerance: NA; Voltage: NA; Wattage: NA; Weight: NA; Datasheet: Y:\MIS_DATABASE\DATASHEETS\ICS\MEMORY\MT40AXX.PDF
U34 = AM654X_BGA784: IC AM65X MICRO CONTROLLER UNIT BGA784; Chkd/date: ALVY/010721; Crtd /date: MANIRAJA/010721; Custom_Duty: 15%; Customs_HS_Code: 85423100; Distributor_name: NA; Distributor_part_number: NA; Footprint Path: Y:\MIS_DATABASE\Library\ALTIUM_TOOL\PCB_FOOTPRINTS\Altium_Footprint_Lib.PcbLib; Height: 1.63MM; Library Path: Y:\MIS_DATABASE\Library\ALTIUM_TOOL\SCHEMATICS_PARTS\MS_MICROCONTROLLER_Library.schlib; Mfr_name: TEXAS INSTRUMENTS; Mistral Part No: 141221070001; Package: BGA784; Part_type: ICS\DIGITAL\MICROCONTROLLER; Project: TI_AM65X_CP; RoHS: NA; Temperature: NA; Tolerance: NA; Voltage: NA; Wattage: NA; Weight: NA; Datasheet: Y:\MIS_DATABASE\DATASHEETS\ICS\DIGITAL\MICROCONTROLLER\MAXWELLM4.PDF

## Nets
DGND: C43.2 C44.2 C45.2 C46.2 C47.2 C53.2 C78.2 C79.2 C80.2 C81.2 C82.2 C83.2 C85.2 C86.2 C87.2 C88.2 C89.2 C90.2 C95.2 C96.2 C97.2 C98.2 C99.2 C100.2 C104.2 C105.2 C106.2 C107.2 C108.2 C112.2 C127.2 C128.2 C129.2 C130.2 C131.2 C132.2 C137.2 C139.2 C140.2 C141.2 C142.2 C154.2 C172.2 C173.2 C174.2 C175.2 C176.2 C177.2 C311.2 C312.2 C315.2 C332.2 C335.2 C338.2 C351.2 C354.2 C355.2 C364.2 C369.2 C370.2 C380.2 C385.2 C387.2 C398.2 C402.2 C411.2 C413.1 C414.2 C415.2 C416.2 C417.2 C418.2 C419.2 C421.2 C422.2 C423.2 C425.2 C426.2 C432.2 C433.2 C434.2 C435.2 C439.2 C442.2 C443.2 C444.2 C445.2 C447.2 C448.2 C449.2 C450.2 C455.2 C459.2 C464.2 C470.2 C472.2 C474.2 C475.2 C478.2 C480.2 C481.1 C495.2 C501.2 C506.2 C507.2 C508.2 C514.2 C519.2 C521.2 C522.2 C523.2 C527.2 C528.2 C536.2 C537.2 C538.2 C540.2 C542.2 C544.2 C545.2 C546.2 C547.2 C548.2 C549.2 C551.2 C552.2 C553.2 C554.2 C555.2 C556.2 C557.2 C558.2 C559.2 C560.2 C561.2 C562.2 C563.2 C564.1 C565.2 C566.2 C567.2 C568.2 C569.2 C570.1 C571.2 C572.2 C573.2 C574.2 C575.2 C576.1 C580.2 C595.2 C729.2 C730.2 C731.2 C732.2 C733.2 C734.2 C735.2 C736.2 C737.2 C738.2 C739.2 C740.2 C741.2 C742.2 C743.2 C744.2 C745.2 R52.2 R75.2 R117.2 R166.2 R484.2 R798.2 U16.A2(VSSQ) U16.A8(VSSQ) U16.A9(VSS) U16.C8(VSS) U16.D1(VSSQ) U16.D9(VSSQ) U16.E1(VSS) U16.E9(VSS) U16.G1(VSS) U16.H9(VSS) U16.K1(VSS) U16.K9(VSS) U16.N1(VSS) U20.A2(VSSQ) U20.A8(VSSQ) U20.A9(VSS) U20.C8(VSS) U20.D1(VSSQ) U20.D9(VSSQ) U20.E1(VSS) U20.E9(VSS) U20.G1(VSS) U20.H9(VSS) U20.K1(VSS) U20.K9(VSS) U20.N1(VSS) U25.A2(VSSQ) U25.A8(VSSQ) U25.A9(VSS) U25.C8(VSS) U25.D1(VSSQ) U25.D9(VSSQ) U25.E1(VSS) U25.E9(VSS) U25.G1(VSS) U25.H9(VSS) U25.K1(VSS) U25.K9(VSS) U25.N1(VSS) U33.A2(VSSQ) U33.A8(VSSQ) U33.A9(VSS) U33.C8(VSS) U33.D1(VSSQ) U33.D9(VSSQ) U33.E1(VSS) U33.E9(VSS) U33.G1(VSS) U33.H9(VSS) U33.K1(VSS) U33.K9(VSS) U33.N1(VSS) U34.A1(VSS) U34.A2(VSS) U34.A28(VSS) U34.AA7(VSS) U34.AA11(VSS) U34.AA13(VSS) U34.AA15(VSS) U34.AA17(VSS) U34.AA19(VSS) U34.AA23(VSS) U34.AA26(VSS) U34.AB10(VSS) U34.AB12(VSS) U34.AB14(VSS) U34.AB16(VSS) U34.AB18(VSS) U34.AB20(VSS) U34.AB22(VSS) U34.AD4(VSS) U34.AE5(VSS) U34.AE10(VSS) U34.AE25(VSS) U34.AF2(VSS) U34.AF8(VSS) U34.AF15(VSS) U34.AF20(VSS) U34.AG1(VSS) U34.AG4(VSS) U34.AG7(VSS) U34.AG10(VSS) U34.AG28(VSS) U34.AH1(VSS) U34.AH2(VSS) U34.AH5(VSS) U34.AH8(VSS) U34.AH11(VSS) U34.AH27(VSS) U34.AH28(VSS) U34.B6(VSS) U34.B9(VSS) U34.B12(VSS) U34.B15(VSS) U34.B20(VSS) U34.D22(VSS) U34.E4(VSS) U34.E26(VSS) U34.E28(VSS) U34.F3(VSS) U34.F14(VSS) U34.F19(VSS) U34.F22(VSS) U34.F25(VSS) U34.F27(VSS) U34.G2(VSS) U34.G7(VSS) U34.G9(VSS) U34.G11(VSS) U34.G13(VSS) U34.G16(VSS) U34.G21(VSS) U34.G23(VSS) U34.H1(VSS) U34.H6(VSS) U34.H8(VSS) U34.H10(VSS) U34.H12(VSS) U34.H14(VSS) U34.H20(VSS) U34.H22(VSS) U34.H24(VSS) U34.H26(VSS) U34.H28(VSS) U34.J7(VSS) U34.J9(VSS) U34.J11(VSS) U34.J13(VSS) U34.J15(VSS) U34.J18(VSS) U34.J21(VSS) U34.J23(VSS) U34.J25(VSS) U34.J27(VSS) U34.K1(VSS) U34.K6(VSS) U34.K8(VSS) U34.K10(VSS) U34.K12(VSS) U34.K14(VSS) U34.K17(VSS) U34.K19(VSS) U34.K22(VSS) U34.K23(VSS) U34.L3(VSS) U34.L7(VSS) U34.L9(VSS) U34.L11(VSS) U34.L13(VSS) U34.L16(VSS) U34.L23(VSS) U34.L24(VSS) U34.L26(VSS) U34.L28(VSS) U34.M8(VSS) U34.M10(VSS) U34.M15(VSS) U34.M17(VSS) U34.M20(VSS) U34.N7(VSS) U34.N9(VSS) U34.N11(VSS) U34.N13(VSS) U34.N16(VSS) U34.N19(VSS) U34.N21(VSS) U34.P6(VSS) U34.P8(VSS) U34.P10(VSS) U34.P12(VSS) U34.P14(VSS) U34.P16(VSS) U34.P18(VSS) U34.P22(VSS) U34.R7(VSS) U34.R9(VSS) U34.R11(VSS) U34.R13(VSS) U34.R15(VSS) U34.R17(VSS) U34.R19(VSS) U34.R21(VSS) U34.T8(VSS) U34.T10(VSS) U34.T12(VSS) U34.T14(VSS) U34.T16(VSS) U34.T18(VSS) U34.T22(VSS) U34.T26(VSS) U34.U3(VSS) U34.U7(VSS) U34.U9(VSS) U34.U11(VSS) U34.U13(VSS) U34.U15(VSS) U34.U17(VSS) U34.U19(VSS) U34.U21(VSS) U34.V6(VSS) U34.V10(VSS) U34.V12(VSS) U34.V14(VSS) U34.V18(VSS) U34.V20(VSS) U34.V22(VSS) U34.W7(VSS) U34.W9(VSS) U34.W11(VSS) U34.W13(VSS) U34.W15(VSS) U34.W17(VSS) U34.W19(VSS) U34.W21(VSS) U34.W23(VSS) U34.Y6(VSS) U34.Y8(VSS) U34.Y12(VSS) U34.Y14(VSS) U34.Y16(VSS) U34.Y18(VSS) U34.Y22(VSS) ; also on sheet 11 12 17 18 19 20 21 22 23 24 25 26 27 28 29 30 31 32 33 34 35 36 37 38 39 40 41 42 43 44
VCC3V3_PREREG: R486.1 ; also on sheet 39 40 41 42
VDD_1V0: FL39.1 ; also on sheet 21 22 23 33 35 42
VDD_CORE: FL19.1 ; also on sheet 12 26 39 41
VDD_DDR4: C44.1 C45.1 C47.1 C53.1 C78.1 C80.1 C81.1 C83.1 C86.1 C87.1 C89.1 C90.1 C95.1 C97.1 C98.1 C100.1 C105.1 C106.1 C108.1 C112.1 C128.1 C129.1 C130.1 C132.1 C139.1 C140.1 C142.1 C154.1 C172.1 C174.1 C175.1 C177.1 C311.1 C312.1 C315.1 C332.1 C335.1 C351.1 C354.1 C355.1 C364.1 C369.1 C380.1 C385.1 C387.1 C398.1 C402.1 C434.1 C447.1 C449.1 C528.1 C538.1 U16.A1(VDD) U16.B2(VDDQ) U16.B8(VDDQ) U16.C1(VDDQ) U16.C7(VDD) U16.C9(VDDQ) U16.E2(VDDQ) U16.E8(VDDQ) U16.F1(VDD) U16.F9(VDD) U16.H1(VDD) U16.J9(VDD) U16.M1(VDD) U16.N9(VDD) U20.A1(VDD) U20.B2(VDDQ) U20.B8(VDDQ) U20.C1(VDDQ) U20.C7(VDD) U20.C9(VDDQ) U20.E2(VDDQ) U20.E8(VDDQ) U20.F1(VDD) U20.F9(VDD) U20.H1(VDD) U20.J9(VDD) U20.M1(VDD) U20.N9(VDD) U25.A1(VDD) U25.B2(VDDQ) U25.B8(VDDQ) U25.C1(VDDQ) U25.C7(VDD) U25.C9(VDDQ) U25.E2(VDDQ) U25.E8(VDDQ) U25.F1(VDD) U25.F9(VDD) U25.H1(VDD) U25.J9(VDD) U25.M1(VDD) U25.N9(VDD) U33.A1(VDD) U33.B2(VDDQ) U33.B8(VDDQ) U33.C1(VDDQ) U33.C7(VDD) U33.C9(VDDQ) U33.E2(VDDQ) U33.E8(VDDQ) U33.F1(VDD) U33.F9(VDD) U33.H1(VDD) U33.J9(VDD) U33.M1(VDD) U33.N9(VDD) ; also on sheet 17 26 42
VDD_DLL_CORE: C575.1 C580.1 FL19.2 FL39.2 U34.G22(VDD_DLL_MMC0) U34.H23(VDD_DLL_MMC1)
VDD_MCU: C443.1 C459.1 C475.1 C571.1 U34.M22(VDD_WKUP1) U34.V11(VDD_WKUP0) U34.W10(VDD_WKUP0) U34.W12(VDD_WKUP0) ; also on sheet 12 26
VDD_MMC1: FL40.1 ; also on sheet 18
VDDA_1P8_OLDI: C566.1 C730.1 FL21.2 U34.L22(VDDA_1P8_OLDI0)
VDDA_1V8: FL21.1 FL22.1 FL23.1 FL24.1 FL26.1 FL27.1 FL28.1 FL29.1 FL30.1 FL31.1 FL32.1 FL33.1 FL34.1 FL35.1 U34.AB6(VDDA_1P8_MON_WKUP) U34.AC6(VDDA_1P8_MON0) ; also on sheet 26
VDDA_3P3_IOLDO_WKUP: C450.1 C729.1 FL16.2 U34.AB9(VDDA_3P3_IOLDO_WKUP)
VDDA_3P3_USB: C464.1 C501.1 FL18.2 U34.AC12(VDDA_3P3_USB)
VDDA_3V3_SDIO: C745.1 FL13.2 FL40.2 U34.H17(VDDA_3P3_SDIO)
VDDA_GP1: C478.1 C495.1 C521.1 C735.1 FL27.2 U34.AA14(VDDA_1P8_SERDES0) U34.AB13(VDDA_1P8_SERDES0) U34.AB15(VDDA_1P8_SERDES0)
VDDA_GP3: C472.1 C737.1 FL30.2 U34.U12(VDDA_MCU)
VDDA_GP4: C556.1 C595.1 C738.1 FL28.2 U34.L20(VDDA_1P8_CSI0) U34.M21(VDDA_1P8_CSI0)
VDDA_GP9: C448.1 C736.1 FL29.2 U34.AA9(VDDA_WKUP)
VDDA_MCU_ADC: C423.1 C444.1 C734.1 FL26.2 U34.M7(VDDA_ADC_MCU) U34.M9(VDDA_ADC_MCU)
VDDA_PLL_DDR: C455.1 C507.1 C740.1 FL32.2 U34.H11(VDDA_PLL1_DDR) U34.H15(VDDA_PLL0_DDR)
VDDA_PLL_DSS: C565.1 C741.1 FL33.2 U34.L21(VDDA_PLL_DSS)
VDDA_PLL_MAIN: C527.1 C742.1 FL34.2 U34.Y17(VDDA_PLL_CORE)
VDDA_PLL_MPU: C474.1 C508.1 C739.1 FL31.2 U34.K15(VDDA_PLL_MPU1) U34.L12(VDDA_PLL_MPU0)
VDDA_PLL_PER0: C422.1 C743.1 FL35.2 U34.AB7(VDDA_PLL_PER0)
VDDA_POR: C445.1 C733.1 FL24.2 U34.Y9(VDDA_POR_WKUP)
VDDA_SRAM_CORE: C519.1 C546.1 C731.1 FL22.2 U34.M19(VDDA_SRAM_CORE0) U34.V16(VDDA_SRAM_CORE1)
VDDA_SRAM_MPU: C419.1 C540.1 C732.1 FL23.2 U34.K7(VDDA_SRAM_MPU0) U34.L18(VDDA_SRAM_MPU1)
VDDA_SYS_MON: R484.1 R486.2 U34.AC11(VDDA_VSYS_MON)
VDDA_WKUP_LDO: R798.1 U34.AB8(VDDA_LDO_WKUP)
VDDS_OSC1: C514.1 C522.1 C744.1 FL36.2 U34.J16(VDDS_OSC1)
VDDSHV_SD_IO: C552.1 C564.2 C572.1 U34.J20(VDDSHV7) U34.J22(VDDSHV7) U34.K21(VDDSHV7) ; also on sheet 12 18
CAP_VDDA_1P8_IOLDO0: U34.AA10(VDDS8) U34.AA16(VDDS1) U34.G12(VDDS0) U34.P20(VDDS2) ; also on sheet 12
CAP_VDDA_1P8_IOLDO_WKUP: U34.V8(VDDS0_WKUP) ; also on sheet 12
CAP_VDDA_1P8_SDIO: U34.G17(VDDA_1P8_SDIO) U34.K20(VDDS7) ; also on sheet 12
DDR_A0: U16.L3(A0) U20.L3(A0) U25.L3(A0) U33.L3(A0) ; also on sheet 17
DDR_A1: U16.L7(A1) U20.L7(A1) U25.L7(A1) U33.L7(A1) ; also on sheet 17
DDR_A2: U16.M3(A2) U20.M3(A2) U25.M3(A2) U33.M3(A2) ; also on sheet 17
DDR_A3: U16.K7(A3) U20.K7(A3) U25.K7(A3) U33.K7(A3) ; also on sheet 17
DDR_A4: U16.K3(A4) U20.K3(A4) U25.K3(A4) U33.K3(A4) ; also on sheet 17
DDR_A5: U16.L8(A5) U20.L8(A5) U25.L8(A5) U33.L8(A5) ; also on sheet 17
DDR_A6: U16.L2(A6) U20.L2(A6) U25.L2(A6) U33.L2(A6) ; also on sheet 17
DDR_A7: U16.M8(A7) U20.M8(A7) U25.M8(A7) U33.M8(A7) ; also on sheet 17
DDR_A8: U16.M2(A8) U20.M2(A8) U25.M2(A8) U33.M2(A8) ; also on sheet 17
DDR_A9: U16.M7(A9) U20.M7(A9) U25.M7(A9) U33.M7(A9) ; also on sheet 17
DDR_A10: U16.J3(A10/AP) U20.J3(A10/AP) U25.J3(A10/AP) U33.J3(A10/AP) ; also on sheet 17
DDR_A11: U16.N2(A11) U20.N2(A11) U25.N2(A11) U33.N2(A11) ; also on sheet 17
DDR_A12: U16.J7(A12/BC_N) U20.J7(A12/BC_N) U25.J7(A12/BC_N) U33.J7(A12/BC_N) ; also on sheet 17
DDR_A13: U16.N8(A13) U20.N8(A13) U25.N8(A13) U33.N8(A13) ; also on sheet 17
DDR_A14_WEn: U16.H2(WE_N/A14) U20.H2(WE_N/A14) U25.H2(WE_N/A14) U33.H2(WE_N/A14) ; also on sheet 17
DDR_A15_CAS: U16.H7(CAS_N/A15) U20.H7(CAS_N/A15) U25.H7(CAS_N/A15) U33.H7(CAS_N/A15) ; also on sheet 17
DDR_A16_RAS: U16.H8(RAS_N/A16) U20.H8(RAS_N/A16) U25.H8(RAS_N/A16) U33.H8(RAS_N/A16) ; also on sheet 17
DDR_A17: U16.N7(A17/NF) U20.N7(A17/NF) U25.N7(A17/NF) U33.N7(A17/NF) ; also on sheet 17
DDR_ACTn: U16.H3(ACT_N) U20.H3(ACT_N) U25.H3(ACT_N) U33.H3(ACT_N) ; also on sheet 17
DDR_ALERTn: U16.L9(ALERT_N) U20.L9(ALERT_N) U25.L9(ALERT_N) U33.L9(ALERT_N) ; also on sheet 17
DDR_BA0: U16.K2(BA0) U20.K2(BA0) U25.K2(BA0) U33.K2(BA0) ; also on sheet 17
DDR_BA1: U16.K8(BA1) U20.K8(BA1) U25.K8(BA1) U33.K8(BA1) ; also on sheet 17
DDR_BG0: U16.J2(BG0) U20.J2(BG0) U25.J2(BG0) U33.J2(BG0) ; also on sheet 17
DDR_BG1: U16.J8(BG1) U20.J8(BG1) U25.J8(BG1) U33.J8(BG1) ; also on sheet 17
DDR_CKE: U16.G3(CKE) U20.G3(CKE) U25.G3(CKE) U33.G3(CKE) ; also on sheet 17
DDR_CKE1: U16.G2(C0/CKE1) U20.G2(C0/CKE1) U25.G2(C0/CKE1) U33.G2(C0/CKE1) ; also on sheet 17
DDR_CLKN: U16.F8(CK_C) U20.F8(CK_C) U25.F8(CK_C) U33.F8(CK_C) ; also on sheet 17
DDR_CLKP: U16.F7(CK_T) U20.F7(CK_T) U25.F7(CK_T) U33.F7(CK_T) ; also on sheet 17
DDR_CS1n: U16.G8(C1/CS1_N) U20.G8(C1/CS1_N) U25.G8(C1/CS1_N) U33.G8(C1/CS1_N) ; also on sheet 17
DDR_CSn: U16.G7(CS_N) U20.G7(CS_N) U25.G7(CS_N) U33.G7(CS_N) ; also on sheet 17
DDR_DM0: U16.A7(NF/NF/DM_N/DBI_N/TDQS_T) ; also on sheet 17
DDR_DM1: U20.A7(NF/NF/DM_N/DBI_N/TDQS_T) ; also on sheet 17
DDR_DM2: U25.A7(NF/NF/DM_N/DBI_N/TDQS_T) ; also on sheet 17
DDR_DM3: U33.A7(NF/NF/DM_N/DBI_N/TDQS_T) ; also on sheet 17
DDR_DQ0: U16.C2(DQ0) ; also on sheet 17
DDR_DQ1: U16.B7(DQ1) ; also on sheet 17
DDR_DQ2: U16.D3(DQ2) ; also on sheet 17
DDR_DQ3: U16.D7(DQ3) ; also on sheet 17
DDR_DQ4: U16.D2(DQ4/NC) ; also on sheet 17
DDR_DQ5: U16.D8(DQ5/NC) ; also on sheet 17
DDR_DQ6: U16.E3(DQ6/NC) ; also on sheet 17
DDR_DQ7: U16.E7(DQ7/NC) ; also on sheet 17
DDR_DQ8: U20.C2(DQ0) ; also on sheet 17
DDR_DQ9: U20.B7(DQ1) ; also on sheet 17
DDR_DQ10: U20.D3(DQ2) ; also on sheet 17
DDR_DQ11: U20.D7(DQ3) ; also on sheet 17
DDR_DQ12: U20.D2(DQ4/NC) ; also on sheet 17
DDR_DQ13: U20.D8(DQ5/NC) ; also on sheet 17
DDR_DQ14: U20.E3(DQ6/NC) ; also on sheet 17
DDR_DQ15: U20.E7(DQ7/NC) ; also on sheet 17
DDR_DQ16: U25.C2(DQ0) ; also on sheet 17
DDR_DQ17: U25.B7(DQ1) ; also on sheet 17
DDR_DQ18: U25.D3(DQ2) ; also on sheet 17
DDR_DQ19: U25.D7(DQ3) ; also on sheet 17
DDR_DQ20: U25.D2(DQ4/NC) ; also on sheet 17
DDR_DQ21: U25.D8(DQ5/NC) ; also on sheet 17
DDR_DQ22: U25.E3(DQ6/NC) ; also on sheet 17
DDR_DQ23: U25.E7(DQ7/NC) ; also on sheet 17
DDR_DQ24: U33.C2(DQ0) ; also on sheet 17
DDR_DQ25: U33.B7(DQ1) ; also on sheet 17
DDR_DQ26: U33.D3(DQ2) ; also on sheet 17
DDR_DQ27: U33.D7(DQ3) ; also on sheet 17
DDR_DQ28: U33.D2(DQ4/NC) ; also on sheet 17
DDR_DQ29: U33.D8(DQ5/NC) ; also on sheet 17
DDR_DQ30: U33.E3(DQ6/NC) ; also on sheet 17
DDR_DQ31: U33.E7(DQ7/NC) ; also on sheet 17
DDR_DQS0_N: U16.B3(DQS_C) ; also on sheet 17
DDR_DQS0_P: U16.C3(DQS_T) ; also on sheet 17
DDR_DQS1_N: U20.B3(DQS_C) ; also on sheet 17
DDR_DQS1_P: U20.C3(DQS_T) ; also on sheet 17
DDR_DQS2_N: U25.B3(DQS_C) ; also on sheet 17
DDR_DQS2_P: U25.C3(DQS_T) ; also on sheet 17
DDR_DQS3_N: U33.B3(DQS_C) ; also on sheet 17
DDR_DQS3_P: U33.C3(DQS_T) ; also on sheet 17
DDR_ODT: U16.F3(ODT) U20.F3(ODT) U25.F3(ODT) U33.F3(ODT) ; also on sheet 17
DDR_ODT1: U16.F2(C2/ODT1) U20.F2(C2/ODT1) U25.F2(C2/ODT1) U33.F2(C2/ODT1) ; also on sheet 17
DDR_PARITY: U16.N3(PAR) U20.N3(PAR) U25.N3(PAR) U33.N3(PAR) ; also on sheet 17
DDR_RESET#: U16.L1(RESET_N) U20.L1(RESET_N) U25.L1(RESET_N) U33.L1(RESET_N) ; also on sheet 17
DDR_TEN: U16.G9(TEN) U20.G9(TEN) U25.G9(TEN) U33.G9(TEN) ; also on sheet 17
DDR_VPP: C43.1 C46.1 C79.1 C85.1 C88.1 C96.1 C104.1 C107.1 C127.1 C137.1 C141.1 C173.1 U16.B1(VPP) U16.M9(VPP) U20.B1(VPP) U20.M9(VPP) U25.B1(VPP) U25.M9(VPP) U33.B1(VPP) U33.M9(VPP) ; also on sheet 17
DDR_VREFCA: C82.1 C99.1 C131.1 C176.1 C338.1 C370.1 C411.1 C544.1 U16.J1(VREFCA) U20.J1(VREFCA) U25.J1(VREFCA) U33.J1(VREFCA) ; also on sheet 17 42
SOC_DVDD1V8: C415.1 C417.1 C418.1 C425.1 C432.1 C435.1 C439.1 C442.1 C537.1 C542.1 C545.1 C547.1 C548.1 C549.1 C551.1 C553.1 C555.1 C557.1 C558.1 C561.1 C562.1 C568.1 C569.1 C570.2 C573.1 C574.1 C576.2 FL36.1 U34.AA20(VDDSHV5) U34.AA22(VDDSHV4) U34.AB19(VDDSHV5) U34.AB21(VDDSHV5) U34.AB23(VDDSHV5) U34.AC18(VDDS5) U34.F20(VDDS6) U34.G20(VDDSHV6) U34.H19(VDDSHV6) U34.H21(VDDSHV6) U34.N6(VDDSHV2_WKUP) U34.N8(VDDS2_WKUP) U34.P7(VDDSHV2_WKUP) U34.P9(VDDSHV2_WKUP) U34.R6(VDDSHV1_WKUP) U34.R8(VDDSHV1_WKUP) U34.T7(VDDSHV1_WKUP) U34.T9(VDDS1_WKUP) U34.T20(VDDS3) U34.T21(VDDSHV3) U34.U20(VDDSHV3) U34.U22(VDDSHV3) U34.V21(VDDSHV3) U34.V23(VDDSHV3) U34.W20(VDDSHV4) U34.W22(VDDSHV4) U34.Y20(VDDS4) U34.Y21(VDDSHV4) U34.Y23(VDDSHV4) ; also on sheet 18 26 38
SoC_DVDD3V3: C413.2 C416.1 C421.1 C426.1 C433.1 C470.1 C480.1 C481.2 C506.1 C523.1 C536.1 C554.1 C560.1 C563.1 C567.1 FL13.1 FL16.1 FL18.1 U34.AA18(VDDSHV1) U34.AA21(VDDA_3P3_IOLDO1) U34.AB11(VDDSHV8) U34.AB17(VDDSHV1) U34.AC10(VDDA_3P3_MON0) U34.G15(VDDSHV0) U34.G18(VDDA_3P3_IOLDO0) U34.H16(VDDSHV0) U34.N20(VDDSHV2) U34.N22(VDDSHV2) U34.P21(VDDSHV2) U34.R20(VDDSHV2) U34.R22(VDDSHV2) U34.U6(VDDA_3P3_MON_WKUP) U34.U8(VDDSHV0_WKUP) U34.V7(VDDSHV0_WKUP) U34.W8(VDDSHV0_WKUP) U34.Y7(VDDSHV0_WKUP) ; also on sheet 26 34
VPP_1V8: FL17.1 ; also on sheet 41
VPP_CORE_MCU: C414.1 C559.1 FL17.2 U34.F21(VPP_CORE) U34.T6(VPP_MCU)
N15808488: R75.1 U20.B9(ZQ)
N15808528: TP8.1(TP) U16.A3(NF/NF/TDQS_C/NF)
N15808578: TP11.1(TP) U20.A3(NF/NF/TDQS_C/NF)
N15808694: TP13.1(TP) U25.A3(NF/NF/TDQS_C/NF)
N15808746: R52.1 U16.B9(ZQ)
N15808770: TP15.1(TP) U33.A3(NF/NF/TDQS_C/NF)
N15812130: R166.1 U33.B9(ZQ)
N15812170: R117.1 U25.B9(ZQ)

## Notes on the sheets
sheet 13
- SoC POWER
- Decaps for VDDA_WKUP pins
- 3.3V IO SUPPLY
- 1.8V Analog SUPPLY
- CORE SUPPLY
- VPP SUPPLY
- 3.3V ANALOG SUPPLY
- OSCILLATOR SUPPLY
sheet 14
- PROCESSOR DECAPS
sheet 15
- SoC POWER - VSS
sheet 16
- DDR4  DEVICE 1
- DDR4  DEVICE 2
- DDR4  DEVICE 3
- DDR4  DEVICE 4
